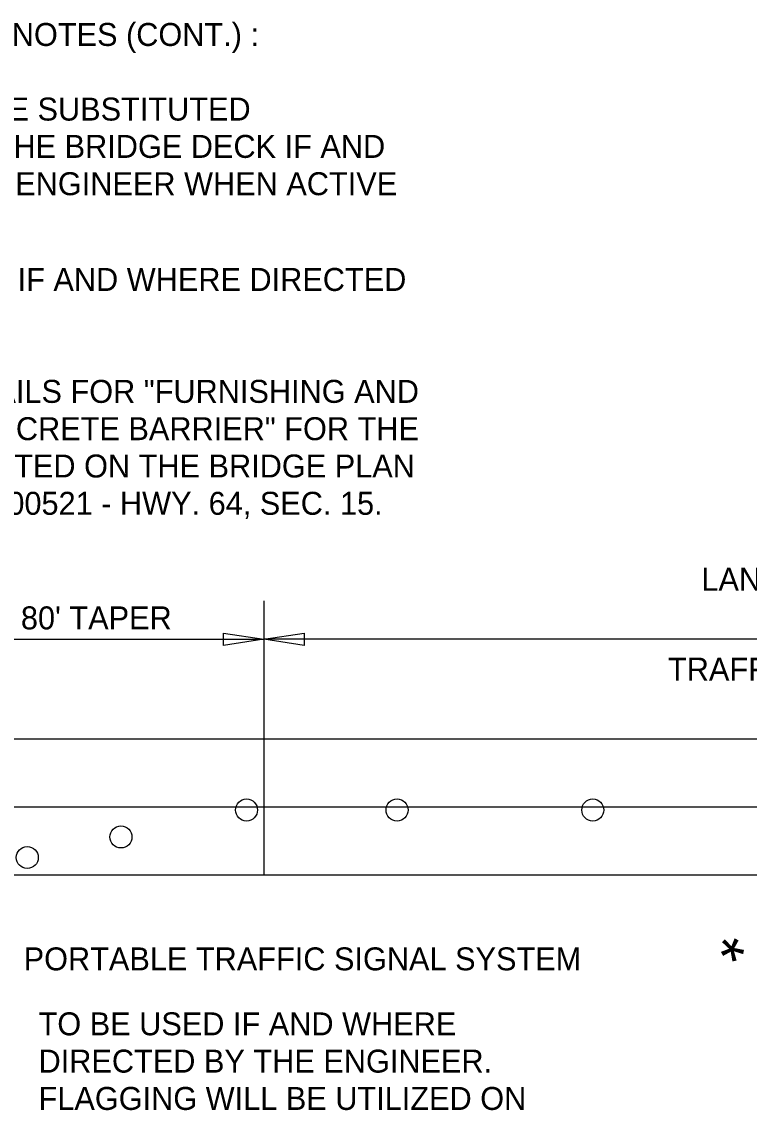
# Model space of a CAD drawing. Extents: x 1927831 to 1930787, y 596452 to 597699.
# Drawn here: x 1928666 to 1928856.2, y 597408.5 to 597692.9 of the extents above; entities that cross this region are included whole.
import ezdxf

# ---------------------------------------------------------------- set-up
doc = ezdxf.new("R2010")
doc.units = 0
doc.layers.add('Default', color=7, linetype='Continuous')
doc.layers.add('R_Border', color=7, linetype='Continuous')

msp = doc.modelspace()

# ---------------------------------------------------------------- linework, layer by layer
at = {"layer": 'Default'}
for p, q in [((1928729.31, 597541.61), (1928729.31, 597481.38)), ((1928655.37, 597531.57), (1928729.31, 597531.57)), ((1928718.76, 597529.98), (1928718.76, 597533.15)), ((1928718.76, 597533.15), (1928729.31, 597531.57)), ((1928729.31, 597531.57), (1928718.76, 597529.98)), ((1928729.31, 597531.57), (1928739.85, 597533.15)), ((1928739.85, 597529.98), (1928729.31, 597531.57)), ((1929173.7, 597531.57), (1928729.31, 597531.57)), ((1928739.85, 597533.15), (1928739.85, 597529.98)), ((1928729.31, 597510.51), (1928729.31, 597470.05)), ((1928044.85, 597505.58), (1929173.7, 597505.58)), ((1927908.3, 597487.79), (1929173.7, 597487.79)), ((1928044.85, 597470), (1929173.7, 597470))]:
    msp.add_line(p, q, dxfattribs=at)
for centre in [(1928724.81, 597486.95), (1928764.17, 597486.95), (1928815.34, 597486.95), (1928691.97, 597479.91), (1928667.47, 597474.54)]:
    msp.add_circle(centre, 2.88, dxfattribs=at)

# ---------------------------------------------------------------- texts
for s, height, p in [('LANE CLOSURE BRIDGE LENGTH + ROADWAY ', 5.9996, (1928843.74, 597544.26)), ("80' TAPER", 6, (1928665.82, 597534.16)), ("TRAFFIC DRUMS @ 40' O.C. IN CLOSED LANE", 5.9996, (1928835.01, 597520.77)), ('PORTABLE TRAFFIC SIGNAL SYSTEM', 6, (1928666.54, 597445.05))]:
    msp.add_text(s, height=height, rotation=360, dxfattribs=at).set_placement(p)
at = {"layer": 'R_Border'}
for s, height, rotation, p in [('MAINTENANCE OF TRAFFIC NOTES (CONT.) :', 6, 360, (1928553.34, 597686.62)), ('5. VERTICAL PANELS MAY BE SUBSTITUTED', 6, 360, (1928553.34, 597667.12)), ('  FOR TRAFFIC DRUMS ON THE BRIDGE DECK IF AND', 6, 360, (1928553.34, 597657.37)), ('  WHERE DIRECTED BY THE ENGINEER WHEN ACTIVE', 6, 360, (1928553.34, 597647.62)), ('6.  FLAGGING MAY BE USED IF AND WHERE DIRECTED', 6, 360, (1928553.05, 597622.6)), ('7.  REFER TO SPECIAL DETAILS FOR "FURNISHING AND', 6, 360, (1928553.05, 597593.35)), ('  INSTALLING PRECAST CONCRETE BARRIER" FOR THE', 6, 360, (1928553.05, 597583.6)), ('  RAILING REPAIR AS INDICATED ON THE BRIDGE PLAN', 6, 360, (1928553.05, 597573.85)), ('  SHEETS FOR BRIDGE # 4 - 00521 - HWY. 64, SEC. 15.', 6, 360, (1928553.05, 597564.1)), ('*', 12, 45, (1928855.76, 597442.1)), ('TO BE USED IF AND WHERE', 6, 360, (1928670.44, 597428.08)), ('DIRECTED BY THE ENGINEER.', 6, 360, (1928670.44, 597418.33)), ('FLAGGING WILL BE UTILIZED ON', 6, 360, (1928670.44, 597408.58))]:
    msp.add_text(s, height=height, rotation=rotation, dxfattribs=at).set_placement(p)

doc.saveas('drawing.dxf')
